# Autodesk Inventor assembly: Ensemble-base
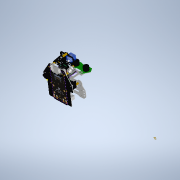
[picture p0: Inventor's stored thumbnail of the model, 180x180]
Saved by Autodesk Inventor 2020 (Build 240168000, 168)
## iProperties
Created: 2021-10
Part Number: Ensemble-base
Document SubType Name: Assembly
Designer: bruno
Mass: 78.0707 g
Surface Area: 663.807 cm^2
Volume: 70.3901 cm^3
Density: 1.10912 g/cm^3
Author: bruno
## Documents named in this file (12)
- C:\Users\bruno\OneDrive\Bureau\Robot-Inventor\Robot-Maqueen\Ensemble-base.iam
- C:\Users\bruno\OneDrive\Bureau\Robot-Inventor\Robot-Maqueen\base.ipt
- C:\Users\bruno\OneDrive\Bureau\Robot-Inventor\Robot-Maqueen\support-roue.ipt
- C:\Users\bruno\OneDrive\Bureau\Robot-Inventor\Robot-Maqueen\ecrou-hexa-2.ipt
- C:\Users\bruno\Documents\Inventor\Content Center Files\R2020\fr-FR\ANSI B18.6.7M(01)\ANSI B18.6.7M - M3x0,5 x 5(5).ipt
- C:\Users\bruno\OneDrive\Bureau\Robot-Inventor\Robot-Maqueen\pile.ipt
- C:\Users\bruno\OneDrive\Bureau\Robot-Inventor\Robot-Maqueen\microbit.ipt
- C:\Users\bruno\OneDrive\Bureau\Robot-Inventor\Robot-Maqueen\Ensemble-final.iam
- C:\Users\bruno\OneDrive\Bureau\Robot-Inventor\Robot-Maqueen\support-capteur.ipt
- C:\Users\bruno\OneDrive\Bureau\Robot-Inventor\Robot-Maqueen\capteur-ultrasons.ipt
- C:\Users\bruno\OneDrive\Bureau\Robot-Inventor\Robot-Maqueen\ecrou-hexa-3.ipt
- C:\Users\bruno\Documents\Inventor\Content Center Files\R2020\fr-FR\ANSI B18.6.7M(01)\ANSI B18.6.7M - M3x0,5 x 4(5).ipt
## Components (19 placed, 11 different names)
1. base:1 — Placage:1, Placage:2, Placage:3, Placage:4, Placage:5, Placage:6, Placage:13, Placage:14, Placage:17, Placage:18, Placage:19, Affleurement:1, Logement:2, Logement:3, Logement:4
2. support-roue:1 — Placage:1, Placage:2, Affleurement:1
3. ecrou-hexa-2:1 — Placage:3, Placage:6, Placage:11, Placage:20, Tangente:2
4. ecrou-hexa-2:2 — Placage:4, Placage:5, Placage:9, Tangente:1
5. Vis à tête tronconique à empreinte cruciforme - Type IA - Métrique M3x0,5 x 5:1 — Placage:9, Placage:22
6. Vis à tête tronconique à empreinte cruciforme - Type IA - Métrique M3x0,5 x 5:2 — Placage:11, Placage:21
7. pile:1 — Placage:13, Placage:14
8. microbit:1 — Placage:17, Placage:18, Placage:19
9. Ensemble-final:1 [sub-assembly] — Placage:20, Tangente:1, Tangente:2, Placage:21, Placage:22
10. support-capteur:1 — Logement:1, Placage:23, Logement:5, Logement:6, Logement:9, Logement:10, Logement:11
11. capteur-ultrasons:1 — Logement:1, Placage:23, Logement:7, Logement:8
12. ecrou-hexa-3:1 — Logement:2
13. ecrou-hexa-3:2 — Logement:3, Logement:6
14. ecrou-hexa-3:3 — Logement:4, Logement:5
15. Vis à tête tronconique à empreinte cruciforme - Type IA - Métrique M3x0,5 x 4:1 — Logement:7
16. Vis à tête tronconique à empreinte cruciforme - Type IA - Métrique M3x0,5 x 4:2 — Logement:8
17. Vis à tête tronconique à empreinte cruciforme - Type IA - Métrique M3x0,5 x 4:3 — Logement:9
18. Vis à tête tronconique à empreinte cruciforme - Type IA - Métrique M3x0,5 x 4:4 — Logement:10
19. Vis à tête tronconique à empreinte cruciforme - Type IA - Métrique M3x0,5 x 4:5 — Logement:11
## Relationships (31: Mate 17, Insert 11, Tangent 2, Flush 1)
- Placage:1 [Mate]: base:1 ↔ support-roue:1
- Placage:2 [Mate]: base:1 ↔ support-roue:1
- Placage:3 [Mate]: base:1 ↔ ecrou-hexa-2:1
- Placage:4 [Mate]: base:1 ↔ ecrou-hexa-2:2
- Placage:5 [Mate]: base:1 ↔ ecrou-hexa-2:2
- Placage:6 [Mate]: base:1 ↔ ecrou-hexa-2:1
- Placage:9 [Mate]: ecrou-hexa-2:2 ↔ Vis à tête tronconique à empreinte cruciforme - Type IA - Métrique M3x0,5 x 5:1
- Placage:11 [Mate]: ecrou-hexa-2:1 ↔ Vis à tête tronconique à empreinte cruciforme - Type IA - Métrique M3x0,5 x 5:2
- Placage:13 [Mate]: base:1 ↔ pile:1
- Placage:14 [Mate]: base:1 ↔ pile:1
- Placage:17 [Mate]: base:1 ↔ microbit:1
- Placage:18 [Mate]: base:1 ↔ microbit:1
- Placage:19 [Mate]: base:1 ↔ microbit:1
- Affleurement:1 [Flush]: base:1 ↔ support-roue:1
- Placage:20 [Mate]: ecrou-hexa-2:1 ↔ Ensemble-final:1
- Tangente:1: ecrou-hexa-2:2 ↔ Ensemble-final:1
- Tangente:2: ecrou-hexa-2:1 ↔ Ensemble-final:1
- Placage:21 [Mate]: Vis à tête tronconique à empreinte cruciforme - Type IA - Métrique M3x0,5 x 5:2 ↔ Ensemble-final:1
- Placage:22 [Mate]: Vis à tête tronconique à empreinte cruciforme - Type IA - Métrique M3x0,5 x 5:1 ↔ Ensemble-final:1
- Logement:1 [Insert]: support-capteur:1 ↔ capteur-ultrasons:1
- Placage:23 [Mate]: support-capteur:1 ↔ capteur-ultrasons:1
- Logement:2 [Insert]: base:1 ↔ ecrou-hexa-3:1
- Logement:3 [Insert]: base:1 ↔ ecrou-hexa-3:2
- Logement:4 [Insert]: base:1 ↔ ecrou-hexa-3:3
- Logement:5 [Insert]: support-capteur:1 ↔ ecrou-hexa-3:3
- Logement:6 [Insert]: support-capteur:1 ↔ ecrou-hexa-3:2
- Logement:7 [Insert]: capteur-ultrasons:1 ↔ Vis à tête tronconique à empreinte cruciforme - Type IA - Métrique M3x0,5 x 4:1
- Logement:8 [Insert]: capteur-ultrasons:1 ↔ Vis à tête tronconique à empreinte cruciforme - Type IA - Métrique M3x0,5 x 4:2
- Logement:9 [Insert]: support-capteur:1 ↔ Vis à tête tronconique à empreinte cruciforme - Type IA - Métrique M3x0,5 x 4:3
- Logement:10 [Insert]: support-capteur:1 ↔ Vis à tête tronconique à empreinte cruciforme - Type IA - Métrique M3x0,5 x 4:4
- Logement:11 [Insert]: support-capteur:1 ↔ Vis à tête tronconique à empreinte cruciforme - Type IA - Métrique M3x0,5 x 4:5
